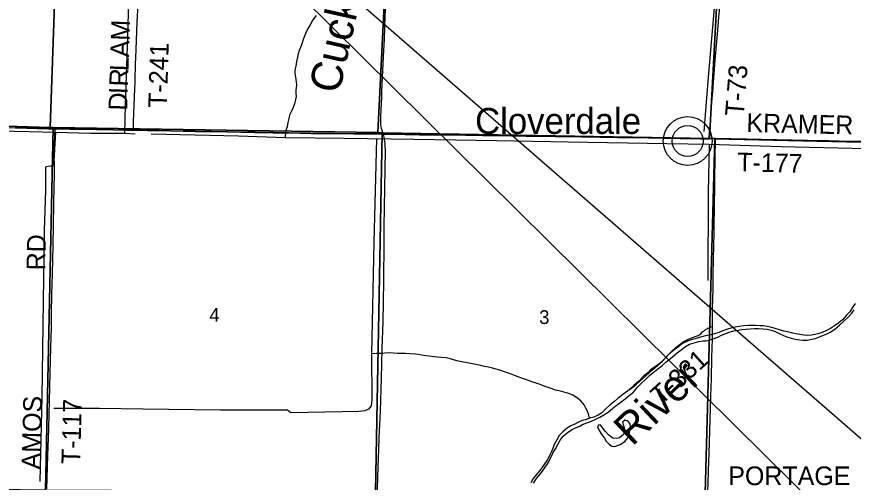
# Model space of a CAD drawing. Extents: x -59 to 43, y 0 to 22.
# Drawn here: x 27.1 to 29.644, y 14.155 to 15.571 of the extents above; entities that cross this region are included whole.
import ezdxf

# ---------------------------------------------------------------- set-up
doc = ezdxf.new("R2010")
doc.units = 0
for name, color, linetype in [('BR_P_Gen_Text', 7, 'Continuous'), ('GM_X_County_Road', 7, 'Continuous'), ('GM_X_Interchange_Ramps', 7, 'Continuous'), ('GM_X_Major_River', 7, 'Continuous'), ('GM_X_Major_River_Text', 7, 'Continuous'), ('GM_X_Minor_Lake', 7, 'Continuous'), ('GM_X_Minor_River', 7, 'Continuous'), ('GM_X_Minor_River_Text', 7, 'Continuous'), ('GM_X_Section', 7, 'Continuous'), ('GM_X_Section_Text', 7, 'Continuous'), ('GM_X_Township_Road', 7, 'Continuous'), ('GM_X_Township_Road_Text', 7, 'Continuous'), ('GM_X_Unincorporated', 7, 'Continuous'), ('GM_X_Unincorporated_Location', 7, 'Continuous'), ('GM_X_Unincorporated_Text', 7, 'Continuous')]:
    doc.layers.add(name, color=color, linetype=linetype)

msp = doc.modelspace()

# ---------------------------------------------------------------- linework, layer by layer
at = {"layer": 'BR_P_Gen_Text'}
msp.add_lwpolyline([(26.8361, 16.7501), (30.1526, 13.8664), (29.75, 13.8664)], close=True, dxfattribs=at)
at = {"layer": 'GM_X_County_Road'}
for points in [[(28.215, 15.2143), (28.2115, 15.2255), (28.2096, 15.231), (28.2083, 15.2367), (28.2075, 15.2428), (28.2073, 15.2459), (28.2072, 15.2521), (28.2077, 15.2676), (28.2095, 15.308), (28.2102, 15.3266), (28.211, 15.3452), (28.2148, 15.4291), (28.2158, 15.4508), (28.2183, 15.5037), (28.2212, 15.572), (28.2225, 15.6124), (28.2257, 15.6807), (28.2273, 15.7118), (28.2276, 15.719)], [(28.1972, 14.1284), (28.1975, 14.1365), (28.1997, 14.2017), (28.2017, 14.2545), (28.203, 14.2918), (28.2065, 14.3725), (28.2094, 14.4719), (28.2106, 14.5154), (28.2121, 14.562), (28.2144, 14.6428), (28.2158, 14.7049), (28.2164, 14.767), (28.2173, 14.8851), (28.2177, 14.9318), (28.2204, 15.1089), (28.2214, 15.1648), (28.2212, 15.1772), (28.2206, 15.1864), (28.219, 15.1979), (28.2164, 15.2104), (28.215, 15.2143)]]:
    msp.add_lwpolyline(points, dxfattribs=at)
at = {"layer": 'GM_X_Interchange_Ramps'}
for points in [[(27.0968, 15.2338), (27.131, 15.233), (27.1621, 15.2323), (27.1963, 15.2314), (27.2171, 15.2311), (27.2336, 15.2309), (27.2615, 15.2301), (27.3051, 15.2296), (27.3424, 15.2286), (27.3952, 15.2277), (27.4356, 15.2268), (27.4549, 15.2266), (27.4978, 15.226), (27.5693, 15.2246), (27.6439, 15.223), (27.7403, 15.2214), (27.8242, 15.2198), (27.8801, 15.219), (27.9268, 15.2184), (27.9952, 15.2173), (28.0667, 15.2165), (28.1257, 15.2155), (28.2148, 15.2149), (28.2812, 15.2139), (28.3247, 15.2131), (28.3837, 15.2125), (28.4646, 15.2113), (28.5174, 15.2109), (28.6045, 15.2098), (28.648, 15.2088), (28.6884, 15.2085), (28.7381, 15.2076), (28.819, 15.2066), (28.9278, 15.2042), (28.9713, 15.2042), (29.1174, 15.2019), (29.1578, 15.2013), (29.1796, 15.2011), (29.2057, 15.2011), (29.2254, 15.2006), (29.3184, 15.199), (29.4582, 15.1961), (29.5048, 15.1952), (29.5701, 15.1935), (29.6322, 15.1921), (29.6757, 15.1914)], [(29.6757, 15.1914), (29.6322, 15.1921), (29.5701, 15.1935), (29.5048, 15.1952), (29.4582, 15.1961), (29.3184, 15.199), (29.2254, 15.2006), (29.2057, 15.2011), (29.1796, 15.2011), (29.1578, 15.2013), (29.1174, 15.2019), (28.9713, 15.2042), (28.9278, 15.2042), (28.819, 15.2066), (28.7381, 15.2076), (28.6884, 15.2085), (28.648, 15.2088), (28.6045, 15.2098), (28.5174, 15.2109), (28.4646, 15.2113), (28.3837, 15.2125), (28.3247, 15.2131), (28.2812, 15.2139), (28.2148, 15.2149), (28.1257, 15.2155), (28.0667, 15.2165), (27.9952, 15.2173), (27.9268, 15.2184), (27.8801, 15.219), (27.8242, 15.2198), (27.7403, 15.2214), (27.6439, 15.223), (27.5693, 15.2246), (27.4978, 15.226), (27.4549, 15.2266), (27.4356, 15.2268), (27.3952, 15.2277), (27.3424, 15.2286), (27.3051, 15.2296), (27.2615, 15.2301), (27.2336, 15.2309), (27.2171, 15.2311), (27.1963, 15.2314), (27.1621, 15.2323), (27.131, 15.233), (27.0968, 15.2338)]]:
    msp.add_lwpolyline(points, dxfattribs=at)
at = {"layer": 'GM_X_Major_River'}
for points in [[(29.65, 14.6988), (29.641, 14.686), (29.6336, 14.674), (29.6242, 14.6635), (29.6111, 14.6491), (29.6007, 14.6404), (29.5876, 14.6311), (29.5753, 14.6226), (29.563, 14.6168), (29.55, 14.6109), (29.537, 14.6066), (29.5271, 14.6049), (29.5175, 14.6031), (29.5061, 14.6018), (29.4936, 14.6028), (29.4815, 14.6046), (29.47, 14.6068), (29.4608, 14.6086), (29.4454, 14.6124), (29.4334, 14.6153), (29.4227, 14.6181), (29.4069, 14.6226), (29.3967, 14.6258), (29.3824, 14.6295), (29.3706, 14.631), (29.3611, 14.6314), (29.3475, 14.6324), (29.3353, 14.6323), (29.3254, 14.6322), (29.312, 14.6309), (29.2986, 14.6291), (29.285, 14.6268), (29.2755, 14.6246), (29.2618, 14.621), (29.2475, 14.6159), (29.2354, 14.6113), (29.2227, 14.6073), (29.2109, 14.6041), (29.1998, 14.602), (29.1865, 14.5985), (29.1769, 14.5952), (29.1639, 14.5917), (29.154, 14.5892), (29.1455, 14.5869), (29.1311, 14.5803), (29.1222, 14.5749), (29.1126, 14.5671), (29.1026, 14.5597), (29.0887, 14.5486), (29.0775, 14.5389), (29.0664, 14.5271), (29.0554, 14.5169), (29.0423, 14.5065), (29.0281, 14.4969), (29.0204, 14.4894), (29.0053, 14.4771), (28.9921, 14.4633), (28.9772, 14.4501), (28.9701, 14.4426), (28.9574, 14.432), (28.9435, 14.422), (28.9285, 14.4105), (28.9188, 14.402), (28.9053, 14.3904), (28.8914, 14.3785), (28.8794, 14.3662), (28.8686, 14.3592), (28.8556, 14.3537), (28.8426, 14.3498), (28.8296, 14.3454), (28.8201, 14.3429), (28.8071, 14.3375), (28.7975, 14.332), (28.7856, 14.3267), (28.7752, 14.321), (28.7621, 14.3094), (28.7501, 14.2971), (28.7427, 14.2843), (28.7348, 14.2704), (28.7312, 14.2606), (28.7272, 14.2504), (28.7217, 14.2387), (28.7157, 14.2255), (28.7056, 14.2117), (28.6997, 14.2019), (28.692, 14.1922), (28.6803, 14.1779), (28.6713, 14.1663), (28.6635, 14.1536)], [(28.6715, 14.153), (28.6812, 14.1662), (28.6933, 14.1804), (28.7015, 14.1924), (28.7186, 14.2179), (28.7232, 14.2286), (28.7309, 14.2439), (28.7391, 14.257), (28.7454, 14.2706), (28.7533, 14.2837), (28.7626, 14.295), (28.7746, 14.3054), (28.7873, 14.3143), (28.7992, 14.3209), (28.8126, 14.3264), (28.8211, 14.3305), (28.8344, 14.3362), (28.8478, 14.3413), (28.8612, 14.3468), (28.8739, 14.353), (28.8861, 14.36), (28.8992, 14.3685), (28.9123, 14.3797), (28.927, 14.3919), (28.937, 14.399), (28.9505, 14.409), (28.9628, 14.4194), (28.9756, 14.4298), (28.9872, 14.4433), (28.9992, 14.4556), (29.012, 14.4679), (29.0245, 14.4797), (29.0359, 14.4891), (29.0486, 14.4988), (29.0621, 14.5099), (29.0746, 14.5204), (29.083, 14.5278), (29.0957, 14.5378), (29.1088, 14.5486), (29.1211, 14.5579), (29.1339, 14.5683), (29.1465, 14.5752), (29.1603, 14.5792), (29.1748, 14.5835), (29.1874, 14.5852), (29.1973, 14.5857), (29.2091, 14.5882), (29.2187, 14.5918), (29.2321, 14.5964), (29.2439, 14.6027), (29.257, 14.6082), (29.27, 14.6133), (29.2814, 14.6157), (29.2951, 14.6182), (29.3054, 14.6199), (29.3176, 14.6208), (29.3309, 14.6221), (29.3435, 14.623), (29.356, 14.6231), (29.3693, 14.6221), (29.3822, 14.6212), (29.3951, 14.6183), (29.4049, 14.6147), (29.4192, 14.6083), (29.4324, 14.6016), (29.4422, 14.598), (29.4558, 14.5936), (29.4679, 14.5907), (29.4816, 14.589), (29.4918, 14.588), (29.504, 14.5874), (29.5135, 14.5892), (29.5286, 14.5927), (29.5397, 14.5965), (29.549, 14.6007), (29.5621, 14.6058), (29.5743, 14.612), (29.5882, 14.6212), (29.6021, 14.6332), (29.6152, 14.6451), (29.6284, 14.6577), (29.64, 14.6701), (29.647, 14.6802)]]:
    msp.add_lwpolyline(points, dxfattribs=at)
at = {"layer": 'GM_X_Minor_Lake'}
msp.add_line((28.8779, 14.3024), (28.8875, 14.2889), dxfattribs=at)
msp.add_lwpolyline([(28.8875, 14.2889), (28.8927, 14.2801), (28.9024, 14.2708), (28.9106, 14.2654), (28.9194, 14.2637), (28.9354, 14.2698), (28.9493, 14.2791), (28.959, 14.2907), (28.9635, 14.3069), (28.9664, 14.324), (28.9654, 14.332), (28.9595, 14.3416), (28.9501, 14.3444), (28.9424, 14.3385), (28.9452, 14.3278), (28.9495, 14.3137), (28.9455, 14.3004), (28.9335, 14.29), (28.9251, 14.2879), (28.9134, 14.2892), (28.8995, 14.2994), (28.8909, 14.3098), (28.8805, 14.3229), (28.8742, 14.3298), (28.87, 14.3291), (28.8665, 14.3239), (28.8705, 14.3143), (28.8779, 14.3024)], dxfattribs=at)
at = {"layer": 'GM_X_Minor_River'}
for points in [[(27.4291, 15.2168), (27.431, 15.3015), (27.4378, 15.5126), (27.4446, 15.7199)], [(29.2271, 15.6682), (29.2187, 15.5631), (29.2034, 15.3879), (29.1902, 15.2225)], [(28.0109, 15.5753), (28.0011, 15.5618), (27.9925, 15.5471), (27.9847, 15.5332), (27.9799, 15.5227), (27.9712, 15.5023), (27.9671, 15.4891), (27.9631, 15.4781), (27.9595, 15.4683), (27.9563, 15.4581), (27.9539, 15.4483), (27.9513, 15.435), (27.9488, 15.421), (27.9463, 15.4093), (27.9458, 15.3998), (27.9482, 15.3872), (27.9506, 15.3739), (27.9508, 15.3629), (27.949, 15.3492), (27.9496, 15.339), (27.9498, 15.3291), (27.9485, 15.3192), (27.9449, 15.3068), (27.9412, 15.2958), (27.9357, 15.2845), (27.9302, 15.2721), (27.9277, 15.2619), (27.9248, 15.2494), (27.9227, 15.2361), (27.9176, 15.223), (27.9169, 15.2045)], [(26.7566, 15.2259), (26.7824, 15.225), (26.8147, 15.2248), (26.882, 15.2266), (26.955, 15.2261), (27.1381, 15.2224), (27.2182, 15.2202), (27.3246, 15.2176), (27.4291, 15.2168), (27.4606, 15.2151)], [(27.2182, 15.2202), (27.2132, 15.133), (27.2115, 15.122), (27.2053, 15.1171), (27.1962, 15.1162), (27.1878, 15.1137), (27.1877, 15.1087), (27.1877, 15.043), (27.1836, 14.9223), (27.1808, 14.7047), (27.1763, 14.4145), (27.1705, 14.1579)], [(27.5088, 15.215), (27.7751, 15.2088), (27.9169, 15.2045), (28.0957, 15.2019), (28.3085, 15.1988), (28.56, 15.1951), (28.7777, 15.1904), (29.0778, 15.1862), (29.2062, 15.1835), (29.4246, 15.1769), (29.7702, 15.1684), (29.9985, 15.1627), (30.1747, 15.1588), (30.3167, 15.1555)], [(28.1945, 15.2005), (28.1861, 14.8842), (28.1793, 14.5455), (28.1798, 14.4057), (28.1783, 14.3882), (28.1702, 14.3781), (28.1594, 14.373), (28.1404, 14.3703), (27.934, 14.3668), (27.9235, 14.3742), (27.719, 14.3748), (27.4846, 14.3775), (27.3516, 14.3795), (27.2133, 14.3793)], [(29.2062, 15.1835), (29.2035, 15.0361), (29.2017, 14.7691)], [(28.8426, 14.3498), (28.8384, 14.3677), (28.8307, 14.3811), (28.8255, 14.3911), (28.8155, 14.4027), (28.8027, 14.4131), (28.7911, 14.4202), (28.7794, 14.425), (28.7684, 14.4282), (28.7537, 14.4323), (28.7389, 14.4356), (28.7261, 14.44), (28.7163, 14.4436), (28.7061, 14.4468), (28.6917, 14.4527), (28.6797, 14.4568), (28.6694, 14.4596), (28.6562, 14.4644), (28.6419, 14.4696), (28.6306, 14.4743), (28.617, 14.4792), (28.6072, 14.4831), (28.5962, 14.4867), (28.5841, 14.4908), (28.5728, 14.4948), (28.5588, 14.4996), (28.5471, 14.5021), (28.535, 14.5053), (28.5225, 14.5078), (28.5119, 14.5103), (28.5017, 14.5124), (28.4911, 14.5145), (28.4759, 14.5174), (28.4589, 14.5207), (28.449, 14.5224), (28.4388, 14.5249), (28.4286, 14.5277), (28.4188, 14.5306), (28.4063, 14.5334), (28.3923, 14.5348), (28.3801, 14.5358), (28.3699, 14.5371), (28.3543, 14.5389), (28.3445, 14.5403), (28.3316, 14.5424), (28.3221, 14.5437), (28.3126, 14.5446), (28.2967, 14.546), (28.2811, 14.5467), (28.2587, 14.5471), (28.2458, 14.5477), (28.2325, 14.5491), (28.22, 14.5478), (28.2097, 14.5468), (28.1941, 14.5467), (28.1793, 14.5455)]]:
    msp.add_lwpolyline(points, dxfattribs=at)
at = {"layer": 'GM_X_Section'}
for points in [[(26.2361, 16.2622), (27.2374, 16.2454), (27.2021, 15.2348), (26.2022, 15.2649), (26.1685, 15.2661)], [(27.2374, 16.2454), (28.2485, 16.2218), (28.1989, 15.2189), (27.2112, 15.2343), (27.2021, 15.2348)], [(29.2609, 16.2051), (29.207, 15.2007), (28.2121, 15.218), (28.1989, 15.2189), (28.2485, 16.2218)], [(30.2413, 16.1837), (30.2026, 15.1773), (29.2229, 15.1998), (29.207, 15.2007), (29.2609, 16.2051)], [(26.2022, 15.2649), (27.2021, 15.2348), (27.2112, 15.2343), (27.188, 14.1311), (26.1894, 14.1445)], [(28.1989, 15.2189), (28.2121, 15.218), (28.1914, 14.1258), (27.188, 14.1311), (27.2112, 15.2343)], [(28.2121, 15.218), (29.207, 15.2007), (29.2229, 15.1998), (29.1944, 14.1224), (28.1914, 14.1258)], [(29.2229, 15.1998), (30.2026, 15.1773), (30.2231, 15.1763), (30.1982, 14.1167), (29.1944, 14.1224)]]:
    msp.add_lwpolyline(points, close=True, dxfattribs=at)
at = {"layer": 'GM_X_Township_Road'}
msp.add_line((29.2256, 15.2001), (29.2059, 15.2005), dxfattribs=at)
for points in [[(27.4633, 15.4722), (27.4642, 15.4991), (27.4657, 15.5264), (27.467, 15.5562), (27.4695, 15.6089), (27.4707, 15.6425), (27.4727, 15.6903), (27.4741, 15.7194), (27.4745, 15.7312), (27.4747, 15.7376)], [(29.2059, 15.2005), (29.2072, 15.2219), (29.2088, 15.2398), (29.2111, 15.2683), (29.2147, 15.3104), (29.2157, 15.3228), (29.2173, 15.3439), (29.2248, 15.4394), (29.2313, 15.5186), (29.2356, 15.5701), (29.2382, 15.5992), (29.2422, 15.65), (29.2431, 15.6674), (29.2432, 15.6736), (29.2431, 15.676), (29.2426, 15.6837)], [(27.4551, 15.226), (27.4552, 15.2287), (27.4553, 15.2326), (27.4559, 15.2519), (27.4578, 15.3034), (27.4585, 15.3252), (27.4597, 15.3544), (27.4602, 15.368), (27.4608, 15.3991), (27.461, 15.4072), (27.4611, 15.4096), (27.4613, 15.4183), (27.4617, 15.4295), (27.4624, 15.4463), (27.4633, 15.4722)], [(26.8535, 15.2381), (26.8826, 15.2378), (26.9323, 15.2367), (27.0007, 15.2352), (27.0535, 15.2341), (27.097, 15.2332), (27.1312, 15.2324), (27.1623, 15.2317), (27.1965, 15.2309), (27.2173, 15.2306)], [(27.1917, 14.1348), (27.1925, 14.1664), (27.1949, 14.2378), (27.1976, 14.3155), (27.1987, 14.3652), (27.1998, 14.4024), (27.2021, 14.4894), (27.2032, 14.5236), (27.2042, 14.5671), (27.2058, 14.623), (27.2064, 14.6696), (27.2074, 14.7255), (27.2092, 14.7907), (27.2107, 14.8746), (27.2129, 15.002), (27.2142, 15.0548), (27.2149, 15.0889), (27.2149, 15.1107), (27.2143, 15.1542), (27.2149, 15.179), (27.2164, 15.2132), (27.217, 15.2257), (27.2173, 15.2306)], [(27.2173, 15.2306), (27.2338, 15.2303), (27.2618, 15.2296), (27.3053, 15.229), (27.3426, 15.228), (27.3954, 15.2272), (27.4358, 15.2263), (27.4551, 15.226)], [(27.4551, 15.226), (27.498, 15.2255), (27.5695, 15.224), (27.6441, 15.2224), (27.7405, 15.2209), (27.8244, 15.2192), (27.8804, 15.2184), (27.927, 15.2179), (27.9954, 15.2167), (28.0669, 15.2159), (28.126, 15.215), (28.215, 15.2143)], [(28.215, 15.2143), (28.2814, 15.2134), (28.3249, 15.2126), (28.384, 15.212), (28.4648, 15.2107), (28.5177, 15.2103), (28.6047, 15.2092), (28.6482, 15.2083), (28.6886, 15.208), (28.7384, 15.207), (28.8192, 15.206), (28.928, 15.2037), (28.9715, 15.2036), (29.1176, 15.2013), (29.1581, 15.2007), (29.1798, 15.2005), (29.2059, 15.2005)], [(29.2161, 14.6296), (29.216, 14.6414), (29.2166, 14.685), (29.2181, 14.744), (29.2186, 14.7813), (29.2196, 14.8404), (29.2203, 14.8684), (29.2212, 14.9212), (29.2225, 15.0052), (29.2229, 15.0469), (29.2233, 15.0766), (29.2244, 15.1419), (29.2256, 15.2001)], [(29.2256, 15.2001), (29.3186, 15.1985), (29.4584, 15.1955), (29.5051, 15.1946), (29.5703, 15.1929), (29.6324, 15.1916), (29.676, 15.1908), (29.7723, 15.1886), (29.8562, 15.1869), (29.9028, 15.1863), (30.0302, 15.1837), (30.0923, 15.1819), (30.2058, 15.1795)], [(29.185, 14.6115), (29.187, 14.6135), (29.1894, 14.6154), (29.1943, 14.6192), (29.1996, 14.6225), (29.2023, 14.6239), (29.2051, 14.6253), (29.2078, 14.6266), (29.2107, 14.6276), (29.2161, 14.6296)], [(29.2021, 14.1234), (29.2025, 14.1318), (29.203, 14.1504), (29.2041, 14.1908), (29.206, 14.2437), (29.2094, 14.3462), (29.2115, 14.4177), (29.2129, 14.4709), (29.2145, 14.5351), (29.2158, 14.5917), (29.2158, 14.601), (29.2161, 14.6166), (29.2161, 14.6296)], [(28.964, 14.4355), (28.9732, 14.4438), (28.9852, 14.4535), (28.9946, 14.4616), (29.0338, 14.4968), (29.0572, 14.5171), (29.0641, 14.5233), (29.0849, 14.5462), (29.0915, 14.5528), (29.1052, 14.5653), (29.1147, 14.5732), (29.1222, 14.5788), (29.1299, 14.584), (29.1353, 14.587), (29.1437, 14.5909), (29.1523, 14.5944), (29.1727, 14.6019), (29.1754, 14.6033), (29.178, 14.605), (29.1804, 14.607), (29.185, 14.6115)]]:
    msp.add_lwpolyline(points, dxfattribs=at)
at = {"layer": 'GM_X_Unincorporated'}
for radius in [0.0744, 0.0472]:
    msp.add_circle((29.1407, 15.1934), radius, dxfattribs=at)
at = {"layer": 'GM_X_Unincorporated_Location'}
msp.add_line((29.1407, 15.1934), (29.1407, 15.1934), dxfattribs=at)

# ---------------------------------------------------------------- texts
at = {"layer": 'GM_X_Major_River_Text'}
msp.add_text('River', height=0.09475, rotation=43.3887, dxfattribs=at).set_placement((28.9719, 14.2626))
at = {"layer": 'GM_X_Minor_River_Text'}
msp.add_text('Cuckle', height=0.09476, rotation=77.4227, dxfattribs=at).set_placement((28.0809, 15.3342))
at = {"layer": 'GM_X_Section_Text'}
for s, p in [('4', (27.6859, 14.6436)), ('3', (28.6892, 14.6367))]:
    msp.add_text(s, height=0.0419, rotation=0, dxfattribs=at).set_placement(p)
at = {"layer": 'GM_X_Township_Road_Text'}
for s, height, rotation, p in [('M', 0.0568, 87.8434, (27.4431, 15.4977)), ('A', 0.0568, 88.0634, (27.4414, 15.4478)), ('T-241', 0.05682, 88.367, (27.557, 15.2936)), ('L', 0.0568, 88.0583, (27.44, 15.4053)), ('T-73', 0.05682, 85.4098, (29.3109, 15.2672)), ('R', 0.0568, 88.0599, (27.4384, 15.3586)), ('I', 0.0568, 88.0641, (27.4376, 15.3353)), ('D', 0.0568, 88.0581, (27.4359, 15.2853)), ('KRAMER', 0.05682, 358.716, (29.3189, 15.2207)), ('T-177', 0.05682, 358.6044, (29.2909, 15.1014)), ('RD', 0.05682, 89.0128, (27.1869, 14.7995)), ('T-331', 0.05682, 42.0274, (29.0603, 14.3885)), ('AMOS', 0.05682, 88.5796, (27.1719, 14.1938)), ('T-117', 0.05682, 88.3199, (27.2928, 14.2097)), ('PORTAGE', 0.05682, 0, (29.2642, 14.1465))]:
    msp.add_text(s, height=height, rotation=rotation, dxfattribs=at).set_placement(p)
at = {"layer": 'GM_X_Unincorporated_Text'}
msp.add_text('Cloverdale', height=0.07898, rotation=0, dxfattribs=at).set_placement((28.4942, 15.2149))

doc.saveas('drawing.dxf')
